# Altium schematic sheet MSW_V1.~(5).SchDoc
size B; Organization: ORGANIZATION; Address1: ADDRESS 1; Address2: ADDRESS 2; Address3: ADDRESS 3; Address4: ADDRESS 4; Revision: -; SheetNumber: 1; SheetTotal: 1; ENG_APP_DATE: --/--/--; DSN_APP_DATE: --/--/--; CHK_APP_DATE: --/--/--
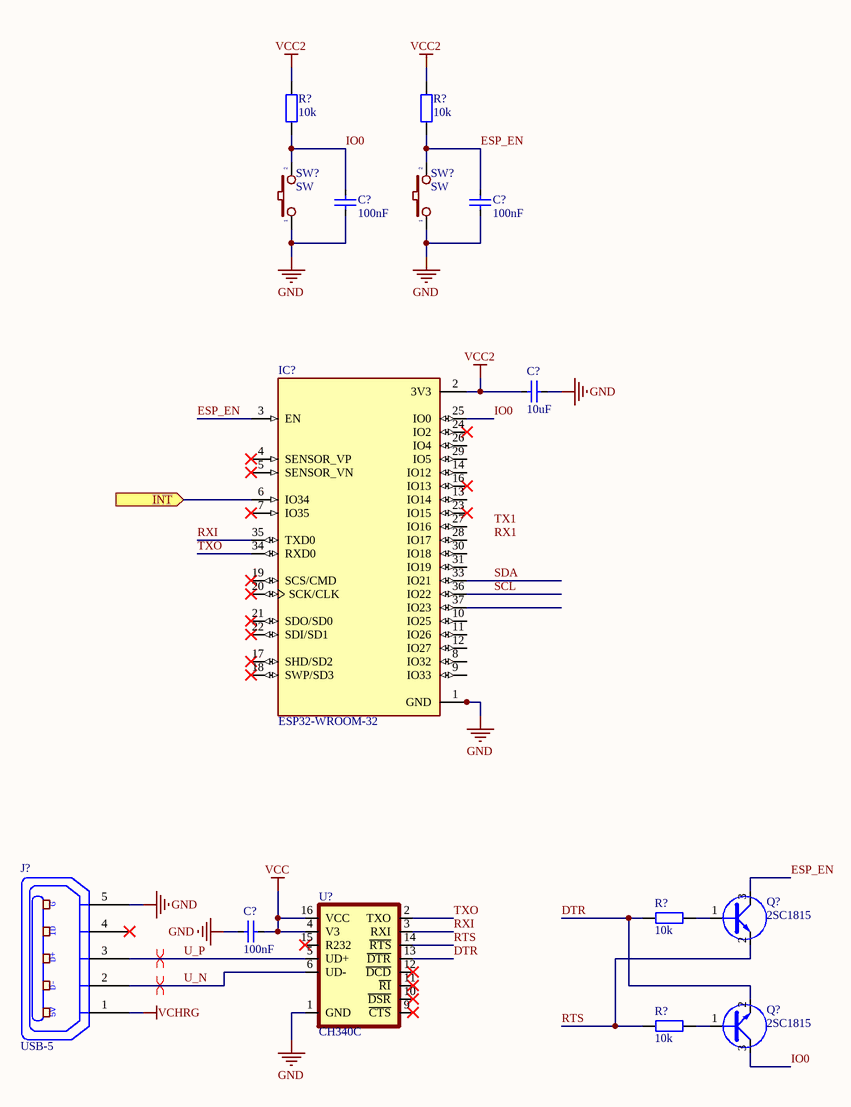
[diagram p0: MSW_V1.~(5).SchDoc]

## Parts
(Parts that share a designator on the sheet are numbered #1, #2 ... from top to bottom, then left to right.)
C?#1  100nF  [CAP_0603]
C?#2  100nF  [CAP_0603]
C?#3  10uF  [CAP_0603]
C?#4  100nF  [CAP_0603]
IC?  ESP32-WROOM-32  [MODULE_ESP32-WROOM-32]
J?  USB-5  [USB-M1]
Q?#1  2SC1815  [SOT23D]
Q?#2  2SC1815  [SOT23D]
R?#1  10k  [RES-SMD-0603]
R?#2  10k  [RES-SMD-0603]
R?#3  10k  [RES-SMD-0603]
R?#4  10k  [RES-SMD-0603]
SW?#1  SW  [SW 3x2x4]
SW?#2  SW  [SW 3x2x4]
U?  CH340C  [SOP-16]

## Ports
INT (in)

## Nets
GND: C?#1.2 C?#2.2 C?#3.2 C?#4.1 IC?.1(GND) IC?.15(GND) IC?.38(GND) IC?.39_1(GND) IC?.39_2(GND) IC?.39_3(GND) IC?.39_4(GND) IC?.39_5(GND) IC?.39_6(GND) IC?.39_7(GND) IC?.39_8(GND) IC?.39_9(GND) IC?.39_10(GND) IC?.39_11(GND) IC?.39_12(GND) IC?.39_13(GND) IC?.39_14(GND) IC?.39_15(GND) IC?.39_16(GND) IC?.39_17(GND) IC?.39_18(GND) IC?.39_19(GND) IC?.39_20(GND) IC?.39_21(GND) J?.5(P5) SW?#1.1 SW?#2.1 U?.1(GND)
VCC: C?#4.2 U?.4(V3) U?.16(VCC)
VCC2: C?#3.1 IC?.2(3V3) R?#1.2 R?#2.2
VCHRG: J?.1(P1)
DTR: Q?#2.2(E) R?#3.2 U?.13(~{DTR})
ESP_EN: C?#2.1 IC?.3(EN) Q?#1.3(C) R?#2.1 SW?#2.2
INT: IC?.6(IO34) ; port INT
IO0: C?#1.1 IC?.25(IO0) Q?#2.3(C) R?#1.1 SW?#1.2
RTS: Q?#1.2(E) R?#4.2 U?.14(~{RTS})
RXI: IC?.35(TXD0) U?.3(RXI)
SCL: IC?.36(IO22)
SDA: IC?.33(IO21)
TXO: IC?.34(RXD0) U?.2(TXO)
U_N: J?.2(P2) U?.6(UD-)
U_P: J?.3(P3) U?.5(UD+)
NetQ?#1_1: Q?#1.1(B) R?#3.1
NetQ?#2_1: Q?#2.1(B) R?#4.1

Not connected (* = marked no-connect by the designer): IC? 4(SENSOR_VP)* 5(SENSOR_VN)* 7(IO35)* 8(IO32) 9(IO33) 10(IO25) 11(IO26) 12(IO27) 13(IO14) 14(IO12) 16(IO13)* 17(SHD/SD2)* 18(SWP/SD3)* 19(SCS/CMD)* 20(SCK/CLK)* 21(SDO/SD0)* 22(SDI/SD1)* 23(IO15)* 24(IO2)* 26(IO4) 27(IO16) 28(IO17) 29(IO5) 30(IO18) 31(IO19) 37(IO23); J? 4(P4)*; U? 9(~{CTS})* 10(~{DSR})* 11(~{RI})* 12(~{DCD})* 15(R232)*

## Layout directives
differential pair: U_N, U_P

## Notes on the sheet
- Labels drawn without touching a wire or pin: RX1, TX1

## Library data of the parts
C?#1-C?#4 = CapSMD: Capacitor; Value: 33p
IC? = ESP32-WROOM-32: Bluetooth, WiFi Transceiver Module 2.4GHz ~ 2.5GHz Surface Mount; MF: Espressif Systems
J? = USB-5: Manufacturer: FCI; Manufacturer Part Number: 10118193-0001LF; Connector Type: USB - micro B; Number of Contacts: 5; Gender: Receptacle; Specifications: USB 2.0; .Creator: MM; .Checked PCB: RF
Q?#1 Q?#2 = C1815: NPN 600mW, ECB; Value: C1815
R?#1-R?#4 = Resistor - SMD: Resistor SMD; Manufacturer: Generic Components; Class: Passive
SW?#1 SW?#2 = SW2: Switch button 2 pin; Value: SW chip 2 pin
U? = CH340C: USB to serial chip CH340; MF: WCH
